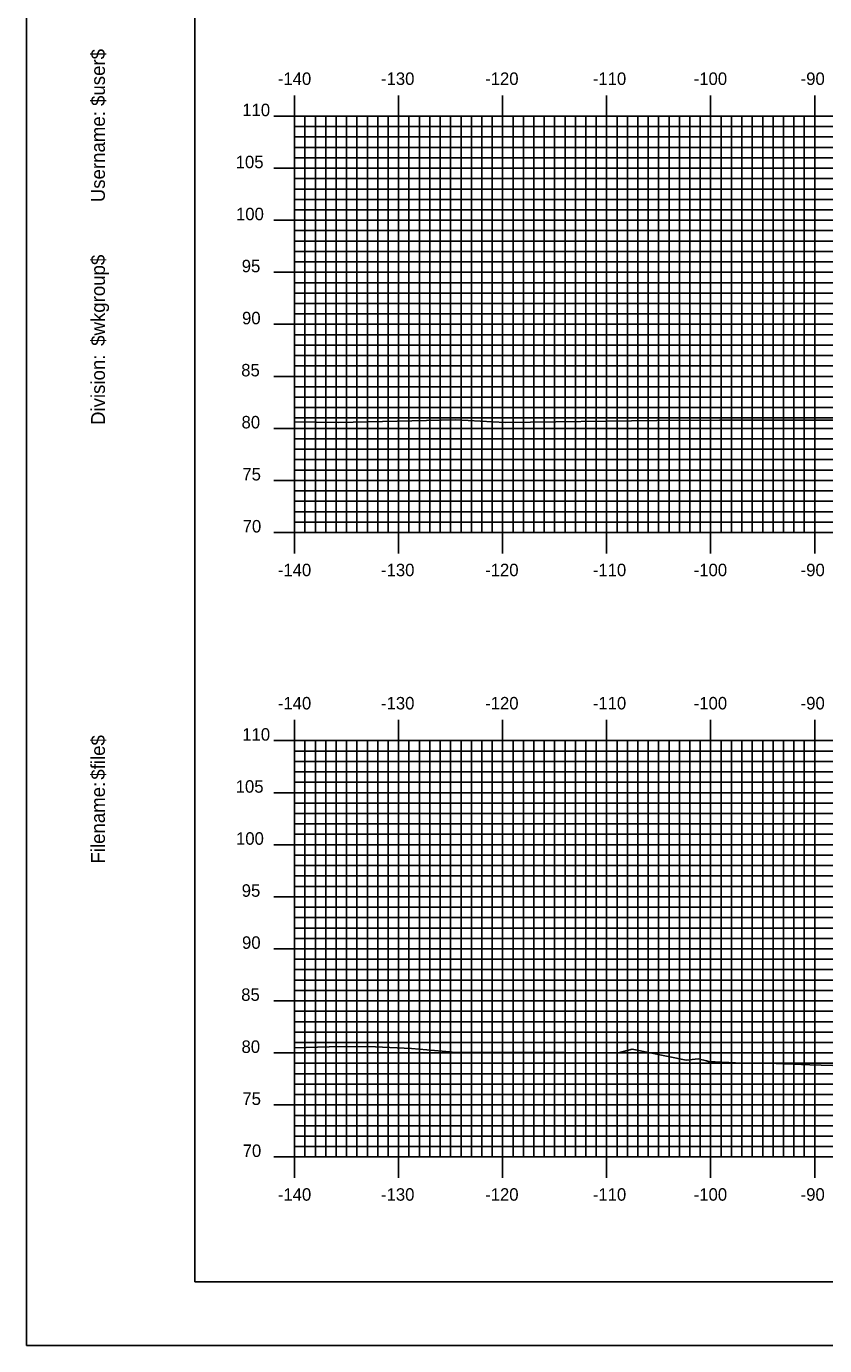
# Model space of a CAD drawing. Extents: x 2846 to 3190, y -1658 to -1438.
# Drawn here: x 2846.4 to 2923.2, y -1657.7 to -1531 of the extents above; entities that cross this region are included whole.
import ezdxf

# ---------------------------------------------------------------- set-up
doc = ezdxf.new("R2010")
doc.units = 0
for name, color, linetype in [('BORDER', 7, 'Continuous'), ('H_V ANNOTATION', 7, 'Continuous'), ('MAJOR', 7, 'Continuous'), ('MINOR', 7, 'Continuous'), ('PLOT BOUNDARY', 7, 'Continuous'), ('S_Roadway_Centerline', 7, 'Continuous')]:
    doc.layers.add(name, color=color, linetype=linetype)

msp = doc.modelspace()

# ---------------------------------------------------------------- linework, layer by layer
at = {"layer": 'BORDER'}
msp.add_lwpolyline([(2862.61, -1651.6), (3182.61, -1651.6), (3182.61, -1441.6), (2862.61, -1441.6)], close=True, dxfattribs=at)
at = {"layer": 'MAJOR'}
for p, q in [((2872.21, -1537.6), (2872.21, -1539.6)), ((2882.21, -1537.6), (2882.21, -1539.6)), ((2892.21, -1537.6), (2892.21, -1539.6)), ((2902.21, -1537.6), (2902.21, -1539.6)), ((2912.21, -1537.6), (2912.21, -1539.6)), ((2922.21, -1537.6), (2922.21, -1539.6)), ((2870.21, -1539.6), (2872.21, -1539.6)), ((2872.21, -1539.6), (3152.21, -1539.6)), ((2872.21, -1579.6), (2872.21, -1539.6)), ((2872.21, -1579.6), (2872.21, -1539.6)), ((2872.21, -1539.6), (3152.21, -1539.6)), ((2882.21, -1579.6), (2882.21, -1539.6)), ((2892.21, -1579.6), (2892.21, -1539.6)), ((2902.21, -1579.6), (2902.21, -1539.6)), ((2912.21, -1579.6), (2912.21, -1539.6)), ((2922.21, -1579.6), (2922.21, -1539.6)), ((2870.21, -1544.6), (2872.21, -1544.6)), ((2872.21, -1544.6), (3152.21, -1544.6)), ((2870.21, -1549.6), (2872.21, -1549.6)), ((2872.21, -1549.6), (3152.21, -1549.6)), ((2870.21, -1554.6), (2872.21, -1554.6)), ((2872.21, -1554.6), (3152.21, -1554.6)), ((2870.21, -1559.6), (2872.21, -1559.6)), ((2872.21, -1559.6), (3152.21, -1559.6)), ((2870.21, -1564.6), (2872.21, -1564.6)), ((2872.21, -1564.6), (3152.21, -1564.6)), ((2870.21, -1569.6), (2872.21, -1569.6)), ((2872.21, -1569.6), (3152.21, -1569.6)), ((2870.21, -1574.6), (2872.21, -1574.6)), ((2872.21, -1574.6), (3152.21, -1574.6)), ((2870.21, -1579.6), (2872.21, -1579.6)), ((2872.21, -1579.6), (3152.21, -1579.6)), ((2872.21, -1579.6), (3152.21, -1579.6)), ((2872.21, -1581.61), (2872.21, -1579.6)), ((2882.21, -1581.61), (2882.21, -1579.6)), ((2892.21, -1581.61), (2892.21, -1579.6)), ((2902.21, -1581.61), (2902.21, -1579.6)), ((2912.21, -1581.61), (2912.21, -1579.6)), ((2922.21, -1581.61), (2922.21, -1579.6)), ((2872.21, -1597.6), (2872.21, -1599.6)), ((2882.21, -1597.6), (2882.21, -1599.6)), ((2892.21, -1597.6), (2892.21, -1599.6)), ((2902.21, -1597.6), (2902.21, -1599.6)), ((2912.21, -1597.6), (2912.21, -1599.6)), ((2922.21, -1597.6), (2922.21, -1599.6)), ((2870.21, -1599.6), (2872.21, -1599.6)), ((2872.21, -1599.6), (3152.21, -1599.6)), ((2872.21, -1639.6), (2872.21, -1599.6)), ((2872.21, -1639.6), (2872.21, -1599.6)), ((2872.21, -1599.6), (3152.21, -1599.6)), ((2882.21, -1639.6), (2882.21, -1599.6)), ((2892.21, -1639.6), (2892.21, -1599.6)), ((2902.21, -1639.6), (2902.21, -1599.6)), ((2912.21, -1639.6), (2912.21, -1599.6)), ((2922.21, -1639.6), (2922.21, -1599.6)), ((2870.21, -1604.6), (2872.21, -1604.6)), ((2872.21, -1604.6), (3152.21, -1604.6)), ((2870.21, -1609.6), (2872.21, -1609.6)), ((2872.21, -1609.6), (3152.21, -1609.6)), ((2870.21, -1614.6), (2872.21, -1614.6)), ((2872.21, -1614.6), (3152.21, -1614.6)), ((2870.21, -1619.6), (2872.21, -1619.6)), ((2872.21, -1619.6), (3152.21, -1619.6)), ((2870.21, -1624.6), (2872.21, -1624.6)), ((2872.21, -1624.6), (3152.21, -1624.6)), ((2870.21, -1629.6), (2872.21, -1629.6)), ((2872.21, -1629.6), (3152.21, -1629.6)), ((2870.21, -1634.6), (2872.21, -1634.6)), ((2872.21, -1634.6), (3152.21, -1634.6)), ((2870.21, -1639.6), (2872.21, -1639.6)), ((2872.21, -1639.6), (3152.21, -1639.6)), ((2872.21, -1639.6), (3152.21, -1639.6)), ((2872.21, -1641.61), (2872.21, -1639.6)), ((2882.21, -1641.61), (2882.21, -1639.6)), ((2892.21, -1641.61), (2892.21, -1639.6)), ((2902.21, -1641.61), (2902.21, -1639.6)), ((2912.21, -1641.61), (2912.21, -1639.6)), ((2922.21, -1641.61), (2922.21, -1639.6))]:
    msp.add_line(p, q, dxfattribs=at)
at = {"layer": 'MINOR'}
for p, q in [((2873.21, -1579.6), (2873.21, -1539.6)), ((2874.21, -1579.6), (2874.21, -1539.6)), ((2875.21, -1579.6), (2875.21, -1539.6)), ((2876.21, -1579.6), (2876.21, -1539.6)), ((2877.21, -1579.6), (2877.21, -1539.6)), ((2878.21, -1579.6), (2878.21, -1539.6)), ((2879.21, -1579.6), (2879.21, -1539.6)), ((2880.21, -1579.6), (2880.21, -1539.6)), ((2881.21, -1579.6), (2881.21, -1539.6)), ((2883.21, -1579.6), (2883.21, -1539.6)), ((2884.21, -1579.6), (2884.21, -1539.6)), ((2885.21, -1579.6), (2885.21, -1539.6)), ((2886.21, -1579.6), (2886.21, -1539.6)), ((2887.21, -1579.6), (2887.21, -1539.6)), ((2888.21, -1579.6), (2888.21, -1539.6)), ((2889.21, -1579.6), (2889.21, -1539.6)), ((2890.21, -1579.6), (2890.21, -1539.6)), ((2891.21, -1579.6), (2891.21, -1539.6)), ((2893.21, -1579.6), (2893.21, -1539.6)), ((2894.21, -1579.6), (2894.21, -1539.6)), ((2895.21, -1579.6), (2895.21, -1539.6)), ((2896.21, -1579.6), (2896.21, -1539.6)), ((2897.21, -1579.6), (2897.21, -1539.6)), ((2898.21, -1579.6), (2898.21, -1539.6)), ((2899.21, -1579.6), (2899.21, -1539.6)), ((2900.21, -1579.6), (2900.21, -1539.6)), ((2901.21, -1579.6), (2901.21, -1539.6)), ((2903.21, -1579.6), (2903.21, -1539.6)), ((2904.21, -1579.6), (2904.21, -1539.6)), ((2905.21, -1579.6), (2905.21, -1539.6)), ((2906.21, -1579.6), (2906.21, -1539.6)), ((2907.21, -1579.6), (2907.21, -1539.6)), ((2908.21, -1579.6), (2908.21, -1539.6)), ((2909.21, -1579.6), (2909.21, -1539.6)), ((2910.21, -1579.6), (2910.21, -1539.6)), ((2911.21, -1579.6), (2911.21, -1539.6)), ((2913.21, -1579.6), (2913.21, -1539.6)), ((2914.21, -1579.6), (2914.21, -1539.6)), ((2915.21, -1579.6), (2915.21, -1539.6)), ((2916.21, -1579.6), (2916.21, -1539.6)), ((2917.21, -1579.6), (2917.21, -1539.6)), ((2918.21, -1579.6), (2918.21, -1539.6)), ((2919.21, -1579.6), (2919.21, -1539.6)), ((2920.21, -1579.6), (2920.21, -1539.6)), ((2921.21, -1579.6), (2921.21, -1539.6)), ((2872.21, -1540.6), (3152.21, -1540.6)), ((2872.21, -1540.6), (2874.22, -1540.6)), ((2872.21, -1541.6), (3152.21, -1541.6)), ((2872.21, -1541.6), (2874.22, -1541.6)), ((2872.21, -1542.6), (3152.21, -1542.6)), ((2872.21, -1542.6), (2874.22, -1542.6)), ((2872.21, -1543.6), (3152.21, -1543.6)), ((2872.21, -1543.6), (2874.22, -1543.6)), ((2872.21, -1545.6), (3152.21, -1545.6)), ((2872.21, -1545.6), (2874.22, -1545.6)), ((2872.21, -1546.6), (3152.21, -1546.6)), ((2872.21, -1546.6), (2874.22, -1546.6)), ((2872.21, -1547.6), (3152.21, -1547.6)), ((2872.21, -1547.6), (2874.22, -1547.6)), ((2872.21, -1548.6), (3152.21, -1548.6)), ((2872.21, -1548.6), (2874.22, -1548.6)), ((2872.21, -1550.6), (3152.21, -1550.6)), ((2872.21, -1550.6), (2874.22, -1550.6)), ((2872.21, -1551.6), (3152.21, -1551.6)), ((2872.21, -1551.6), (2874.22, -1551.6)), ((2872.21, -1552.6), (3152.21, -1552.6)), ((2872.21, -1552.6), (2874.22, -1552.6)), ((2872.21, -1553.6), (3152.21, -1553.6)), ((2872.21, -1553.6), (2874.22, -1553.6)), ((2872.21, -1555.6), (3152.21, -1555.6)), ((2872.21, -1555.6), (2874.22, -1555.6)), ((2872.21, -1556.6), (3152.21, -1556.6)), ((2872.21, -1556.6), (2874.22, -1556.6)), ((2872.21, -1557.6), (3152.21, -1557.6)), ((2872.21, -1557.6), (2874.22, -1557.6)), ((2872.21, -1558.6), (3152.21, -1558.6)), ((2872.21, -1558.6), (2874.22, -1558.6)), ((2872.21, -1560.6), (3152.21, -1560.6)), ((2872.21, -1560.6), (2874.22, -1560.6)), ((2872.21, -1561.6), (3152.21, -1561.6)), ((2872.21, -1561.6), (2874.22, -1561.6)), ((2872.21, -1562.6), (3152.21, -1562.6)), ((2872.21, -1562.6), (2874.22, -1562.6)), ((2872.21, -1563.6), (3152.21, -1563.6)), ((2872.21, -1563.6), (2874.22, -1563.6)), ((2872.21, -1565.6), (3152.21, -1565.6)), ((2872.21, -1565.6), (2874.22, -1565.6)), ((2872.21, -1566.6), (3152.21, -1566.6)), ((2872.21, -1566.6), (2874.22, -1566.6)), ((2872.21, -1567.6), (3152.21, -1567.6)), ((2872.21, -1567.6), (2874.22, -1567.6)), ((2872.21, -1568.6), (3152.21, -1568.6)), ((2872.21, -1568.6), (2874.22, -1568.6)), ((2872.21, -1570.6), (3152.21, -1570.6)), ((2872.21, -1570.6), (2874.22, -1570.6)), ((2872.21, -1571.6), (3152.21, -1571.6)), ((2872.21, -1571.6), (2874.22, -1571.6)), ((2872.21, -1572.6), (3152.21, -1572.6)), ((2872.21, -1572.6), (2874.22, -1572.6)), ((2872.21, -1573.6), (3152.21, -1573.6)), ((2872.21, -1573.6), (2874.22, -1573.6)), ((2872.21, -1575.6), (3152.21, -1575.6)), ((2872.21, -1575.6), (2874.22, -1575.6)), ((2872.21, -1576.6), (3152.21, -1576.6)), ((2872.21, -1576.6), (2874.22, -1576.6)), ((2872.21, -1577.6), (3152.21, -1577.6)), ((2872.21, -1577.6), (2874.22, -1577.6)), ((2872.21, -1578.6), (3152.21, -1578.6)), ((2872.21, -1578.6), (2874.22, -1578.6)), ((2872.21, -1600.6), (3152.21, -1600.6)), ((2872.21, -1600.6), (2874.22, -1600.6)), ((2873.21, -1639.6), (2873.21, -1599.6)), ((2874.21, -1639.6), (2874.21, -1599.6)), ((2875.21, -1639.6), (2875.21, -1599.6)), ((2876.21, -1639.6), (2876.21, -1599.6)), ((2877.21, -1639.6), (2877.21, -1599.6)), ((2878.21, -1639.6), (2878.21, -1599.6)), ((2879.21, -1639.6), (2879.21, -1599.6)), ((2880.21, -1639.6), (2880.21, -1599.6)), ((2881.21, -1639.6), (2881.21, -1599.6)), ((2883.21, -1639.6), (2883.21, -1599.6)), ((2884.21, -1639.6), (2884.21, -1599.6)), ((2885.21, -1639.6), (2885.21, -1599.6)), ((2886.21, -1639.6), (2886.21, -1599.6)), ((2887.21, -1639.6), (2887.21, -1599.6)), ((2888.21, -1639.6), (2888.21, -1599.6)), ((2889.21, -1639.6), (2889.21, -1599.6)), ((2890.21, -1639.6), (2890.21, -1599.6)), ((2891.21, -1639.6), (2891.21, -1599.6)), ((2893.21, -1639.6), (2893.21, -1599.6)), ((2894.21, -1639.6), (2894.21, -1599.6)), ((2895.21, -1639.6), (2895.21, -1599.6)), ((2896.21, -1639.6), (2896.21, -1599.6)), ((2897.21, -1639.6), (2897.21, -1599.6)), ((2898.21, -1639.6), (2898.21, -1599.6)), ((2899.21, -1639.6), (2899.21, -1599.6)), ((2900.21, -1639.6), (2900.21, -1599.6)), ((2901.21, -1639.6), (2901.21, -1599.6)), ((2903.21, -1639.6), (2903.21, -1599.6)), ((2904.21, -1639.6), (2904.21, -1599.6)), ((2905.21, -1639.6), (2905.21, -1599.6)), ((2906.21, -1639.6), (2906.21, -1599.6)), ((2907.21, -1639.6), (2907.21, -1599.6)), ((2908.21, -1639.6), (2908.21, -1599.6)), ((2909.21, -1639.6), (2909.21, -1599.6)), ((2910.21, -1639.6), (2910.21, -1599.6)), ((2911.21, -1639.6), (2911.21, -1599.6)), ((2913.21, -1639.6), (2913.21, -1599.6)), ((2914.21, -1639.6), (2914.21, -1599.6)), ((2915.21, -1639.6), (2915.21, -1599.6)), ((2916.21, -1639.6), (2916.21, -1599.6)), ((2917.21, -1639.6), (2917.21, -1599.6)), ((2918.21, -1639.6), (2918.21, -1599.6)), ((2919.21, -1639.6), (2919.21, -1599.6)), ((2920.21, -1639.6), (2920.21, -1599.6)), ((2921.21, -1639.6), (2921.21, -1599.6)), ((2872.21, -1601.6), (3152.21, -1601.6)), ((2872.21, -1601.6), (2874.22, -1601.6)), ((2872.21, -1602.6), (3152.21, -1602.6)), ((2872.21, -1602.6), (2874.22, -1602.6)), ((2872.21, -1603.6), (3152.21, -1603.6)), ((2872.21, -1603.6), (2874.22, -1603.6)), ((2872.21, -1605.6), (3152.21, -1605.6)), ((2872.21, -1605.6), (2874.22, -1605.6)), ((2872.21, -1606.6), (3152.21, -1606.6)), ((2872.21, -1606.6), (2874.22, -1606.6)), ((2872.21, -1607.6), (3152.21, -1607.6)), ((2872.21, -1607.6), (2874.22, -1607.6)), ((2872.21, -1608.6), (3152.21, -1608.6)), ((2872.21, -1608.6), (2874.22, -1608.6)), ((2872.21, -1610.6), (3152.21, -1610.6)), ((2872.21, -1610.6), (2874.22, -1610.6)), ((2872.21, -1611.6), (3152.21, -1611.6)), ((2872.21, -1611.6), (2874.22, -1611.6)), ((2872.21, -1612.6), (3152.21, -1612.6)), ((2872.21, -1612.6), (2874.22, -1612.6)), ((2872.21, -1613.6), (3152.21, -1613.6)), ((2872.21, -1613.6), (2874.22, -1613.6)), ((2872.21, -1615.6), (3152.21, -1615.6)), ((2872.21, -1615.6), (2874.22, -1615.6)), ((2872.21, -1616.6), (3152.21, -1616.6)), ((2872.21, -1616.6), (2874.22, -1616.6)), ((2872.21, -1617.6), (3152.21, -1617.6)), ((2872.21, -1617.6), (2874.22, -1617.6)), ((2872.21, -1618.6), (3152.21, -1618.6)), ((2872.21, -1618.6), (2874.22, -1618.6)), ((2872.21, -1620.6), (3152.21, -1620.6)), ((2872.21, -1620.6), (2874.22, -1620.6)), ((2872.21, -1621.6), (3152.21, -1621.6)), ((2872.21, -1621.6), (2874.22, -1621.6)), ((2872.21, -1622.6), (3152.21, -1622.6)), ((2872.21, -1622.6), (2874.22, -1622.6)), ((2872.21, -1623.6), (3152.21, -1623.6)), ((2872.21, -1623.6), (2874.22, -1623.6)), ((2872.21, -1625.6), (3152.21, -1625.6)), ((2872.21, -1625.6), (2874.22, -1625.6)), ((2872.21, -1626.6), (3152.21, -1626.6)), ((2872.21, -1626.6), (2874.22, -1626.6)), ((2872.21, -1627.6), (3152.21, -1627.6)), ((2872.21, -1627.6), (2874.22, -1627.6)), ((2872.21, -1628.6), (3152.21, -1628.6)), ((2872.21, -1628.6), (2874.22, -1628.6)), ((2872.21, -1630.6), (3152.21, -1630.6)), ((2872.21, -1630.6), (2874.22, -1630.6)), ((2872.21, -1631.6), (3152.21, -1631.6)), ((2872.21, -1631.6), (2874.22, -1631.6)), ((2872.21, -1632.6), (3152.21, -1632.6)), ((2872.21, -1632.6), (2874.22, -1632.6)), ((2872.21, -1633.6), (3152.21, -1633.6)), ((2872.21, -1633.6), (2874.22, -1633.6)), ((2872.21, -1635.6), (3152.21, -1635.6)), ((2872.21, -1635.6), (2874.22, -1635.6)), ((2872.21, -1636.6), (3152.21, -1636.6)), ((2872.21, -1636.6), (2874.22, -1636.6)), ((2872.21, -1637.6), (3152.21, -1637.6)), ((2872.21, -1637.6), (2874.22, -1637.6)), ((2872.21, -1638.6), (3152.21, -1638.6)), ((2872.21, -1638.6), (2874.22, -1638.6))]:
    msp.add_line(p, q, dxfattribs=at)
at = {"layer": 'PLOT BOUNDARY'}
msp.add_lwpolyline([(2846.43, -1657.72), (3186.43, -1657.72), (3186.43, -1437.72), (2846.43, -1437.72)], close=True, dxfattribs=at)
at = {"layer": 'S_Roadway_Centerline'}
for points in [[(2872.21, -1568.96), (2876.43, -1569.03), (2887.71, -1568.78), (2892.45, -1569.04), (2907.03, -1568.85), (2913.06, -1568.81), (2923.46, -1568.8), (2929.56, -1568.81), (2943.58, -1568.84), (2955.7, -1568.75), (2961.47, -1568.7), (2976.73, -1568.46), (2979.51, -1568.46), (2983.3, -1568.34), (2995.08, -1568.13), (2998.34, -1568.28), (3003.1, -1568.25)], [(2872.21, -1629.12), (2875.53, -1629.01), (2879.27, -1628.98), (2883.45, -1629.19), (2887.15, -1629.5), (2887.36, -1629.52), (2887.88, -1629.55), (2898.11, -1629.55), (2903.36, -1629.6), (2904.68, -1629.25), (2909.86, -1630.3), (2911, -1630.16), (2911.82, -1630.37), (2912, -1630.43), (2915.23, -1630.57), (2917.7, -1630.57), (2921.74, -1630.76), (2925.05, -1630.84)]]:
    msp.add_lwpolyline(points, dxfattribs=at)

# ---------------------------------------------------------------- texts
at = {"layer": 'BORDER'}
for s, p in [('$user$', (2853.98, -1538.62)), ('Username:', (2853.98, -1547.87)), ('$wkgroup$', (2853.98, -1561.67)), ('Division:', (2853.98, -1569.27)), ('$file$', (2853.98, -1603.35)), ('Filename:', (2853.98, -1611.41))]:
    msp.add_text(s, height=1.339, rotation=90, dxfattribs=at).set_placement(p)
at = {"layer": 'H_V ANNOTATION'}
for s, p in [('-140', (2870.6, -1536.6)), ('-130', (2880.52, -1536.6)), ('-120', (2890.53, -1536.6)), ('-110', (2900.88, -1536.6)), ('-100', (2910.58, -1536.6)), ('-90', (2920.86, -1536.6)), ('110', (2867.18, -1539.6)), ('105', (2866.55, -1544.6)), ('100', (2866.58, -1549.6)), ('95', (2867.13, -1554.6)), ('90', (2867.16, -1559.6)), ('85', (2867.08, -1564.6)), ('80', (2867.11, -1569.6)), ('75', (2867.19, -1574.6)), ('70', (2867.22, -1579.6)), ('-140', (2870.6, -1583.8)), ('-130', (2880.52, -1583.8)), ('-120', (2890.53, -1583.8)), ('-110', (2900.88, -1583.8)), ('-100', (2910.58, -1583.8)), ('-90', (2920.86, -1583.8)), ('-140', (2870.6, -1596.6)), ('-130', (2880.52, -1596.6)), ('-120', (2890.53, -1596.6)), ('-110', (2900.88, -1596.6)), ('-100', (2910.58, -1596.6)), ('-90', (2920.86, -1596.6)), ('110', (2867.18, -1599.6)), ('105', (2866.55, -1604.6)), ('100', (2866.58, -1609.6)), ('95', (2867.13, -1614.6)), ('90', (2867.16, -1619.6)), ('85', (2867.08, -1624.6)), ('80', (2867.11, -1629.6)), ('75', (2867.19, -1634.6)), ('70', (2867.22, -1639.6)), ('-140', (2870.6, -1643.8)), ('-130', (2880.52, -1643.8)), ('-120', (2890.53, -1643.8)), ('-110', (2900.88, -1643.8)), ('-100', (2910.58, -1643.8)), ('-90', (2920.86, -1643.8))]:
    msp.add_text(s, height=1.2, dxfattribs=at).set_placement(p)
at = {"layer": 'MAJOR'}
for p in [(2872.2, -1579.6), (2872.2, -1639.6)]:
    msp.add_text('-', height=0.012, dxfattribs=at).set_placement(p)

doc.saveas('drawing.dxf')
